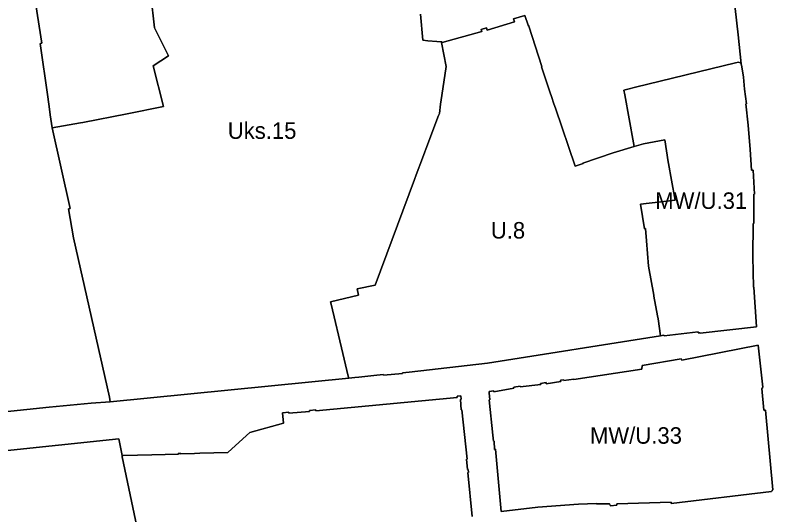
# Model space of a CAD drawing. Extents: x 7423367 to 7424726, y 5546744 to 5548391.
# Drawn here: x 7423725.3 to 7423954.8, y 5547370 to 5547521.4 of the extents above; entities that cross this region are included whole.
import ezdxf

# ---------------------------------------------------------------- set-up
doc = ezdxf.new("R2010")
doc.units = 0
doc.layers.add('linie_rozgraniczajace', color=7, linetype='Continuous')
doc.layers.add('oznaczenia_przeznaczen', color=7, linetype='Continuous')

msp = doc.modelspace()

# ---------------------------------------------------------------- linework, layer by layer
at = {"layer": 'linie_rozgraniczajace'}
for points in [[(7423726.04, 5547555.81), (7423758.63, 5547558.18), (7423763.08, 5547558.56), (7423763.72, 5547548.88), (7423765.6, 5547535.06), (7423765.64, 5547534.69), (7423766.34, 5547527.57), (7423767.5, 5547517.6), (7423771.76, 5547509.04), (7423767.07, 5547506.04), (7423770.15, 5547493.68), (7423759.15, 5547491.46), (7423745.76, 5547488.88), (7423745.02, 5547488.75), (7423736.48, 5547487.27), (7423736.28, 5547488.56), (7423735.89, 5547491.17), (7423735.65, 5547492.87), (7423735.11, 5547496.61), (7423732.81, 5547512.77), (7423733.35, 5547512.87), (7423728.69, 5547542.72), (7423728.28, 5547545.46), (7423727.47, 5547551.35)], [(7423820.8, 5547434.5), (7423829.25, 5547436.59), (7423828.83, 5547438.43), (7423834.3, 5547439.61), (7423846.25, 5547471.59), (7423846.78, 5547472.99), (7423848.69, 5547478.09), (7423849.39, 5547479.96), (7423849.71, 5547480.82), (7423853.54, 5547490.96), (7423853.78, 5547491.6), (7423854.08, 5547494.47), (7423854.47, 5547497.08), (7423855.78, 5547505.88), (7423854.4, 5547513.09), (7423854.59, 5547513.14), (7423866.59, 5547516.45), (7423866.44, 5547517.03), (7423868.01, 5547517.51), (7423868.24, 5547516.86), (7423876.52, 5547519.37), (7423876.27, 5547520.29), (7423879.68, 5547521.31), (7423880.63, 5547518.37), (7423880.92, 5547518.08), (7423884.84, 5547505.82), (7423884.68, 5547505.76), (7423887.34, 5547497.89), (7423887.74, 5547496.71), (7423888.49, 5547494.49), (7423888.91, 5547493.26), (7423894.87, 5547475.61), (7423897.31, 5547476.4), (7423897.26, 5547476.56), (7423906.41, 5547479.66), (7423912.74, 5547481.58), (7423915.58, 5547482.45), (7423922.03, 5547483.63), (7423923.09, 5547476.98), (7423923.19, 5547476.44), (7423924.11, 5547471.4), (7423925.21, 5547465.38), (7423920.86, 5547464.86), (7423914.71, 5547464.14), (7423915.89, 5547456.68), (7423916.21, 5547456.71), (7423916.5, 5547452.98), (7423917.11, 5547445.29), (7423918.7, 5547436.58), (7423918.76, 5547436.26), (7423919.85, 5547430.31), (7423920.02, 5547429.39), (7423920.76, 5547424.21), (7423868.37, 5547415.97), (7423844.66, 5547413.24), (7423842.64, 5547413.02), (7423842.65, 5547412.83), (7423836.83, 5547412.33), (7423836.82, 5547412.46), (7423834.78, 5547412.29), (7423829.35, 5547411.71), (7423828.16, 5547411.59), (7423826.33, 5547411.4), (7423826.19, 5547411.97), (7423824.52, 5547418.83), (7423820.96, 5547433.83)], [(7423909.65, 5547498.67), (7423910.89, 5547498.97), (7423913.2, 5547499.54), (7423943.52, 5547506.94), (7423944.41, 5547507.16), (7423944.92, 5547506.99), (7423945.24, 5547506.65), (7423945.38, 5547505.75), (7423945.88, 5547502.58), (7423946.25, 5547499.01), (7423946.16, 5547498.98), (7423946.84, 5547494.55), (7423946.59, 5547494.51), (7423947.34, 5547488.08), (7423947.92, 5547480.71), (7423948.32, 5547474.39), (7423948.8, 5547474.45), (7423949.22, 5547467.18), (7423949.04, 5547467.16), (7423949.04, 5547458.31), (7423948.82, 5547458.3), (7423948.75, 5547448.27), (7423948.89, 5547438.96), (7423949.07, 5547438.96), (7423949.8, 5547426.96), (7423932.73, 5547424.99), (7423932.71, 5547425.16), (7423932.19, 5547425.1), (7423932.16, 5547425.42), (7423921.84, 5547424.21), (7423921.78, 5547424.38), (7423920.76, 5547424.21), (7423920.02, 5547429.39), (7423919.85, 5547430.31), (7423918.76, 5547436.26), (7423918.7, 5547436.58), (7423917.11, 5547445.29), (7423916.5, 5547452.98), (7423916.21, 5547456.71), (7423915.89, 5547456.68), (7423914.71, 5547464.14), (7423920.86, 5547464.86), (7423925.21, 5547465.38), (7423924.11, 5547471.4), (7423923.19, 5547476.44), (7423923.09, 5547476.98), (7423922.03, 5547483.63), (7423915.58, 5547482.45), (7423912.74, 5547481.58), (7423912.54, 5547482.7), (7423909.91, 5547497.23)], [(7423868.87, 5547404.78), (7423869.07, 5547404.8), (7423868.88, 5547406.92), (7423868.84, 5547407.34), (7423870.23, 5547407.53), (7423870.27, 5547407.29), (7423876.36, 5547408.39), (7423876.31, 5547408.64), (7423878.21, 5547408.92), (7423878.22, 5547408.77), (7423884.48, 5547409.52), (7423884.44, 5547409.81), (7423886.08, 5547410.09), (7423886.14, 5547409.7), (7423890.56, 5547410.36), (7423890.49, 5547410.75), (7423891.49, 5547410.89), (7423891.51, 5547410.69), (7423894.48, 5547411.09), (7423894.51, 5547410.94), (7423915.14, 5547414.15), (7423915.17, 5547415.2), (7423927.04, 5547417.21), (7423927.22, 5547416.89), (7423950.36, 5547421.35), (7423951.75, 5547408.68), (7423951.61, 5547408.66), (7423951.65, 5547408.33), (7423951.48, 5547408.3), (7423952.01, 5547401.66), (7423952.53, 5547401.69), (7423954.79, 5547377.56), (7423954.68, 5547377.56), (7423954.6, 5547377.3), (7423954.38, 5547377.15), (7423954.38, 5547377.1), (7423924.02, 5547373.41), (7423923.98, 5547373.86), (7423907.54, 5547373.35), (7423907.56, 5547372.93), (7423905.57, 5547372.75), (7423905.34, 5547373.3), (7423901.34, 5547373.29), (7423901.33, 5547373.4), (7423895.89, 5547373.18), (7423883.61, 5547372.27), (7423872.5, 5547370.97), (7423870.74, 5547389.83), (7423870.45, 5547389.82), (7423870.35, 5547392.3), (7423870.13, 5547392.29), (7423869.95, 5547394.13)], [(7423868.87, 5547404.78), (7423869.95, 5547394.13), (7423870.13, 5547392.29), (7423870.35, 5547392.3), (7423870.45, 5547389.82), (7423870.74, 5547389.83), (7423872.5, 5547370.97), (7423883.61, 5547372.27), (7423895.89, 5547373.18), (7423901.33, 5547373.4), (7423901.34, 5547373.29), (7423905.34, 5547373.3), (7423905.57, 5547372.75), (7423907.56, 5547372.93), (7423907.54, 5547373.35), (7423923.98, 5547373.86), (7423924.02, 5547373.41), (7423954.38, 5547377.1), (7423954.38, 5547377.15), (7423954.6, 5547377.3), (7423954.68, 5547377.56), (7423954.79, 5547377.56), (7423952.53, 5547401.69), (7423952.01, 5547401.66), (7423951.48, 5547408.3), (7423951.65, 5547408.33), (7423951.61, 5547408.66), (7423951.75, 5547408.68), (7423950.36, 5547421.35), (7423927.22, 5547416.89), (7423927.04, 5547417.21), (7423915.17, 5547415.2), (7423915.14, 5547414.15), (7423894.51, 5547410.94), (7423894.48, 5547411.09), (7423891.51, 5547410.69), (7423891.49, 5547410.89), (7423890.49, 5547410.75), (7423890.56, 5547410.36), (7423886.14, 5547409.7), (7423886.08, 5547410.09), (7423884.44, 5547409.81), (7423884.48, 5547409.52), (7423878.22, 5547408.77), (7423878.21, 5547408.92), (7423876.31, 5547408.64), (7423876.36, 5547408.39), (7423870.27, 5547407.29), (7423870.23, 5547407.53), (7423868.84, 5547407.34), (7423868.88, 5547406.92), (7423869.07, 5547404.8)]]:
    msp.add_lwpolyline(points, close=True, dxfattribs=at)
for points in [[(7423724.4, 5547549.81), (7423727.47, 5547551.35), (7423728.28, 5547545.46), (7423728.69, 5547542.72), (7423733.35, 5547512.87), (7423732.81, 5547512.77), (7423735.11, 5547496.61), (7423735.65, 5547492.87), (7423735.89, 5547491.17), (7423736.28, 5547488.56), (7423736.48, 5547487.27), (7423741.93, 5547462.77), (7423741.4, 5547462.68), (7423742.95, 5547453.93), (7423753.89, 5547405.68), (7423754.09, 5547404.21), (7423748.29, 5547403.79), (7423735.54, 5547402.61), (7423717.1, 5547400.73)], [(7423717.1, 5547400.73), (7423735.54, 5547402.61), (7423748.29, 5547403.79), (7423754.09, 5547404.21), (7423826.33, 5547411.4), (7423828.16, 5547411.59), (7423829.35, 5547411.71), (7423834.78, 5547412.29), (7423836.82, 5547412.46), (7423836.83, 5547412.33), (7423842.65, 5547412.83), (7423842.64, 5547413.02), (7423844.66, 5547413.24), (7423868.37, 5547415.97), (7423920.76, 5547424.21), (7423921.78, 5547424.38), (7423921.84, 5547424.21), (7423932.16, 5547425.42), (7423932.19, 5547425.1), (7423932.71, 5547425.16), (7423932.73, 5547424.99), (7423949.8, 5547426.96), (7423949.07, 5547438.96), (7423948.89, 5547438.96), (7423948.75, 5547448.27), (7423948.82, 5547458.3), (7423949.04, 5547458.31), (7423949.04, 5547467.16), (7423949.22, 5547467.18), (7423948.8, 5547474.45), (7423948.32, 5547474.39), (7423947.92, 5547480.71), (7423947.34, 5547488.08), (7423946.59, 5547494.51), (7423946.84, 5547494.55), (7423946.16, 5547498.98), (7423946.25, 5547499.01), (7423945.88, 5547502.58), (7423945.38, 5547505.75), (7423945.24, 5547506.65), (7423944.31, 5547515.44), (7423940.37, 5547550.19)], [(7423940.37, 5547550.19), (7423944.31, 5547515.44), (7423945.24, 5547506.65), (7423944.92, 5547506.99), (7423944.41, 5547507.16), (7423943.52, 5547506.94), (7423913.2, 5547499.54), (7423910.89, 5547498.97), (7423909.65, 5547498.67), (7423909.91, 5547497.23), (7423912.54, 5547482.7), (7423912.74, 5547481.58), (7423906.41, 5547479.66), (7423897.26, 5547476.56), (7423897.31, 5547476.4), (7423894.87, 5547475.61), (7423888.91, 5547493.26), (7423888.49, 5547494.49), (7423887.74, 5547496.71), (7423887.34, 5547497.89), (7423884.68, 5547505.76), (7423884.84, 5547505.82), (7423880.92, 5547518.08), (7423880.63, 5547518.37), (7423879.68, 5547521.31), (7423876.27, 5547520.29), (7423876.52, 5547519.37), (7423868.24, 5547516.86), (7423868.01, 5547517.51), (7423866.44, 5547517.03), (7423866.59, 5547516.45), (7423854.59, 5547513.14), (7423854.56, 5547513.29), (7423852.96, 5547513.42), (7423850.23, 5547513.66), (7423848.81, 5547513.78), (7423848.07, 5547521.71)], [(7423848.07, 5547521.71), (7423848.81, 5547513.78), (7423850.23, 5547513.66), (7423852.96, 5547513.42), (7423854.56, 5547513.29), (7423854.59, 5547513.14), (7423854.4, 5547513.09), (7423855.78, 5547505.88), (7423854.47, 5547497.08), (7423854.08, 5547494.47), (7423853.78, 5547491.6), (7423853.54, 5547490.96), (7423849.71, 5547480.82), (7423849.39, 5547479.96), (7423848.69, 5547478.09), (7423846.78, 5547472.99), (7423846.25, 5547471.59), (7423834.3, 5547439.61), (7423828.83, 5547438.43), (7423829.25, 5547436.59), (7423820.8, 5547434.5), (7423820.96, 5547433.83), (7423824.52, 5547418.83), (7423826.19, 5547411.97), (7423826.33, 5547411.4), (7423754.09, 5547404.21), (7423753.89, 5547405.68), (7423742.95, 5547453.93), (7423741.4, 5547462.68), (7423741.93, 5547462.77), (7423736.48, 5547487.27), (7423745.02, 5547488.75), (7423745.76, 5547488.88), (7423759.15, 5547491.46), (7423770.15, 5547493.68), (7423767.07, 5547506.04), (7423771.76, 5547509.04), (7423767.5, 5547517.6), (7423766.34, 5547527.57)], [(7423863.66, 5547369.51), (7423862.4, 5547382.77), (7423862.58, 5547382.78), (7423862.48, 5547383.74), (7423862.31, 5547383.72), (7423861.97, 5547386.87), (7423862.17, 5547386.89), (7423860.61, 5547401.81), (7423860.41, 5547401.79), (7423860.12, 5547404.98), (7423860.33, 5547405), (7423860.25, 5547406.07), (7423859.15, 5547405.94), (7423859.21, 5547405.55), (7423816.35, 5547401.49), (7423816.33, 5547401.82), (7423814.43, 5547401.64), (7423814.45, 5547401.32), (7423808.14, 5547400.75), (7423808.12, 5547401.08), (7423806.23, 5547400.89), (7423806.52, 5547397.71), (7423796.4, 5547394.89), (7423791.97, 5547390.97), (7423789.65, 5547388.91), (7423781.22, 5547388.64), (7423779.63, 5547388.59), (7423775.5, 5547388.45), (7423775.49, 5547388.6), (7423774.69, 5547388.54), (7423774.7, 5547388.39), (7423766.69, 5547388.15), (7423757.99, 5547387.96), (7423757.63, 5547387.95), (7423756.67, 5547393.03), (7423669.04, 5547383.82)], [(7423775.28, 5547304.1), (7423757.71, 5547387.52), (7423757.63, 5547387.95), (7423757.99, 5547387.96), (7423766.69, 5547388.15), (7423774.7, 5547388.39), (7423774.69, 5547388.54), (7423775.49, 5547388.6), (7423775.5, 5547388.45), (7423779.63, 5547388.59), (7423781.22, 5547388.64), (7423789.65, 5547388.91), (7423791.97, 5547390.97), (7423796.4, 5547394.89), (7423806.52, 5547397.71), (7423806.23, 5547400.89), (7423808.12, 5547401.08), (7423808.14, 5547400.75), (7423814.45, 5547401.32), (7423814.43, 5547401.64), (7423816.33, 5547401.82), (7423816.35, 5547401.49), (7423859.21, 5547405.55), (7423859.15, 5547405.94), (7423860.25, 5547406.07), (7423860.33, 5547405), (7423860.12, 5547404.98), (7423860.41, 5547401.79), (7423860.61, 5547401.81), (7423862.17, 5547386.89), (7423861.97, 5547386.87), (7423862.31, 5547383.72), (7423862.48, 5547383.74), (7423862.58, 5547382.78), (7423862.4, 5547382.77), (7423863.66, 5547369.51)], [(7423664.51, 5547355.5), (7423657.58, 5547379.7), (7423658.91, 5547382.75), (7423669.04, 5547383.82), (7423756.67, 5547393.03), (7423757.63, 5547387.95), (7423757.71, 5547387.52), (7423775.28, 5547304.1)]]:
    msp.add_lwpolyline(points, dxfattribs=at)

# ---------------------------------------------------------------- texts
at = {"layer": 'oznaczenia_przeznaczen'}
for s, p in [('Uks.15', (7423789.66, 5547483.91)), ('MW/U.31', (7423919.16, 5547462.69)), ('U.8', (7423869.35, 5547453.7)), ('MW/U.33', (7423899.4, 5547391.53))]:
    msp.add_text(s, height=5, dxfattribs=at).set_placement(p)

doc.saveas('drawing.dxf')
